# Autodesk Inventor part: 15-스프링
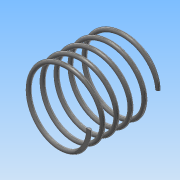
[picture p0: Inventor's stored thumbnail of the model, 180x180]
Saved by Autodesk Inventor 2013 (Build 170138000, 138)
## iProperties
Created: 2015-11
Part Number: 15-스프링
Material: 강철, 탄소
Document SubType Name: Modeling
Designer: Administrator
Density: 7.87 g/cm^3
Mass: 1.53352 g
Surface Area: 7.86938 cm^2
Volume: 0.194856 cm^3
Author: Administrator
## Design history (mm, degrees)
sketch "스케치1"
  geometry: L1 (8, 16.67)-(0, 16.67); L2 (0, 16.67)-(0, 0); L3 (0, 0)-(8, 0); L4 (8, 0)-(8, 16.67); C1 r 0.5 at (8, 0)
  constraints: 8 end point, 2 parallel, 1 centre point, 1 coincident, 1 horizontal, 1 perpendicular
  dimensions: "d0" = 16 diameter of L4 L2; "d2" = 16.66987 distance between parallel lines of L3 L1 (derived); "d3" = 1 diameter of C1
feature "코일1" sketch "스케치1" pitch "d4" = 10; turns "d6" = 5; dims "d5" = 16.66987 (= d2), "d7" = 0, angle "d8" = 90 deg, angle "d9" = 90 deg, "d10" = 0, "d11" = 0
sketch "스케치2"
  geometry: L1 (0, 10)-(16.67, 10); L2 (16.67, 10)-(16.67, -10); L3 (16.67, -10)-(0, -10); L4 (0, -10)-(0, 10); 4 further points
  constraints: 8 end point, 2 coincident, 2 midpoint, 2 parallel, 1 horizontal, 1 perpendicular
  dimensions: "d12" = 20 distance between parallel lines of L3 L1
extrude "돌출1" sketch "스케치2" stored distance "d15" = 0; taper "d16" = 0 deg
node "솔리드1"
